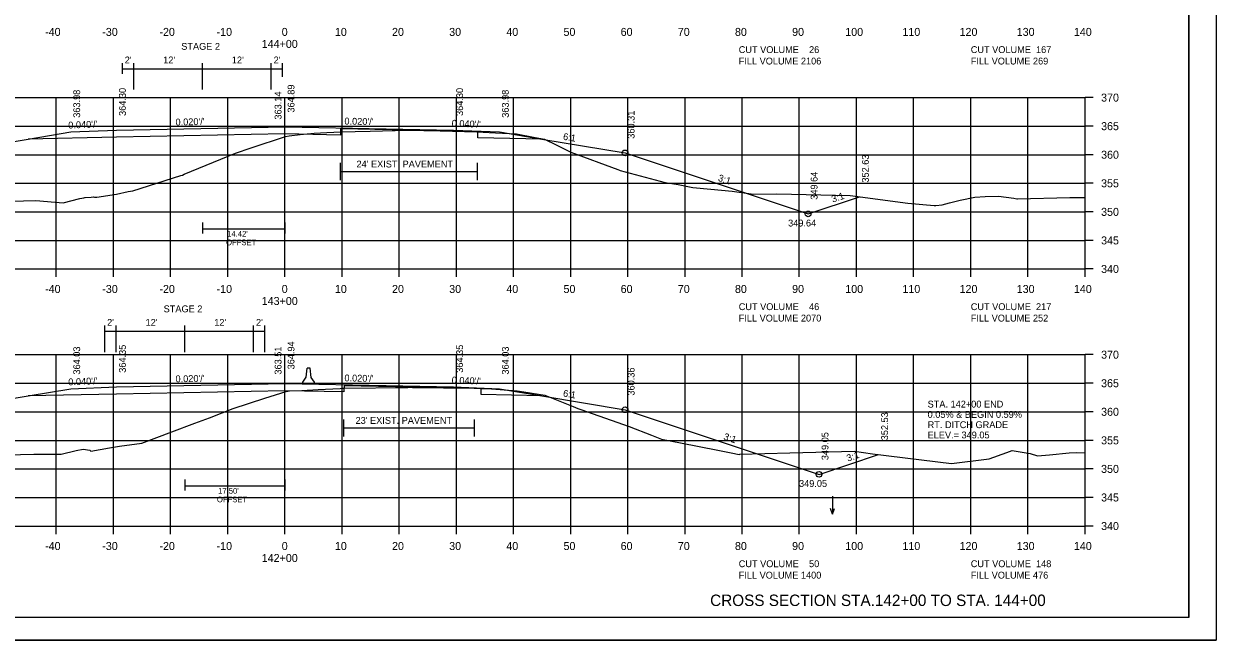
# Model space of a CAD drawing. Extents: x 1374859 to 1376773, y 382242 to 389804.
# Drawn here: x 1376088.9 to 1376297.5, y 386081.8 to 386189.7 of the extents above; entities that cross this region are included whole.
import ezdxf

# ---------------------------------------------------------------- set-up
doc = ezdxf.new("R2010")
doc.units = 0
for name, color, linetype in [('R_Axis', 7, 'Continuous'), ('R_Axis Annot', 7, 'Continuous'), ('R_Border', 7, 'Continuous'), ('R_Border Notes', 7, 'Continuous'), ('R_Detour Annot', 7, 'Continuous'), ('R_Draft', 7, 'Continuous'), ('R_Exist Surface', 7, 'Continuous'), ('R_Fin Surface', 7, 'Continuous'), ('R_Grid', 7, 'Continuous'), ('R_MOT', 7, 'Continuous'), ('R_No Plot', 7, 'Continuous'), ('R_Water Annot', 7, 'Continuous'), ('R_Xsect Elev', 7, 'Continuous'), ('R_Xsect Slope', 7, 'Continuous')]:
    doc.layers.add(name, color=color, linetype=linetype)

msp = doc.modelspace()

# ---------------------------------------------------------------- linework, layer by layer
at = {"layer": 'R_Axis'}
for p, q in [((1376274.57, 386146.8), (1376274.57, 386176.8)), ((1376275.97, 386176.8), (1376274.57, 386176.8)), ((1376275.97, 386171.8), (1376274.57, 386171.8)), ((1376275.97, 386166.8), (1376274.57, 386166.8)), ((1376275.97, 386161.8), (1376274.57, 386161.8)), ((1376275.97, 386156.8), (1376274.57, 386156.8)), ((1376275.97, 386151.8), (1376274.57, 386151.8)), ((1375994.57, 386146.8), (1376274.57, 386146.8)), ((1376094.57, 386145.4), (1376094.57, 386146.8)), ((1376104.57, 386145.4), (1376104.57, 386146.8)), ((1376114.57, 386145.4), (1376114.57, 386146.8)), ((1376124.57, 386145.4), (1376124.57, 386146.8)), ((1376134.57, 386145.4), (1376134.57, 386146.8)), ((1376144.57, 386145.4), (1376144.57, 386146.8)), ((1376154.57, 386145.4), (1376154.57, 386146.8)), ((1376164.57, 386145.4), (1376164.57, 386146.8)), ((1376174.57, 386145.4), (1376174.57, 386146.8)), ((1376184.57, 386145.4), (1376184.57, 386146.8)), ((1376194.57, 386145.4), (1376194.57, 386146.8)), ((1376204.57, 386145.4), (1376204.57, 386146.8)), ((1376214.57, 386145.4), (1376214.57, 386146.8)), ((1376224.57, 386145.4), (1376224.57, 386146.8)), ((1376234.57, 386145.4), (1376234.57, 386146.8)), ((1376244.57, 386145.4), (1376244.57, 386146.8)), ((1376254.57, 386145.4), (1376254.57, 386146.8)), ((1376264.57, 386145.4), (1376264.57, 386146.8)), ((1376274.57, 386145.4), (1376274.57, 386146.8)), ((1376275.97, 386146.8), (1376274.57, 386146.8)), ((1376274.57, 386101.8), (1376274.57, 386131.8)), ((1376275.97, 386131.8), (1376274.57, 386131.8)), ((1376275.97, 386126.8), (1376274.57, 386126.8)), ((1376275.97, 386121.8), (1376274.57, 386121.8)), ((1376275.97, 386116.8), (1376274.57, 386116.8)), ((1376275.97, 386111.8), (1376274.57, 386111.8)), ((1376275.97, 386106.8), (1376274.57, 386106.8)), ((1375994.57, 386101.8), (1376274.57, 386101.8)), ((1376094.57, 386100.4), (1376094.57, 386101.8)), ((1376104.57, 386100.4), (1376104.57, 386101.8)), ((1376114.57, 386100.4), (1376114.57, 386101.8)), ((1376124.57, 386100.4), (1376124.57, 386101.8)), ((1376134.57, 386100.4), (1376134.57, 386101.8)), ((1376144.57, 386100.4), (1376144.57, 386101.8)), ((1376154.57, 386100.4), (1376154.57, 386101.8)), ((1376164.57, 386100.4), (1376164.57, 386101.8)), ((1376174.57, 386100.4), (1376174.57, 386101.8)), ((1376184.57, 386100.4), (1376184.57, 386101.8)), ((1376194.57, 386100.4), (1376194.57, 386101.8)), ((1376204.57, 386100.4), (1376204.57, 386101.8)), ((1376214.57, 386100.4), (1376214.57, 386101.8)), ((1376224.57, 386100.4), (1376224.57, 386101.8)), ((1376234.57, 386100.4), (1376234.57, 386101.8)), ((1376244.57, 386100.4), (1376244.57, 386101.8)), ((1376254.57, 386100.4), (1376254.57, 386101.8)), ((1376264.57, 386100.4), (1376264.57, 386101.8)), ((1376274.57, 386100.4), (1376274.57, 386101.8)), ((1376275.97, 386101.8), (1376274.57, 386101.8))]:
    msp.add_line(p, q, dxfattribs=at)
at = {"layer": 'R_Border'}
for q in [(1376292.75, 386291.26), (1375976.57, 386085.8)]:
    msp.add_line((1376292.75, 386085.8), q, dxfattribs=at)
at = {"layer": 'R_Border Notes'}
for points in [[(1376144.22, 386165.36), (1376144.22, 386162.36)], [(1376168.22, 386165.36), (1376168.22, 386162.36)], [(1376144.22, 386163.86), (1376168.22, 386163.86)], [(1376144.8, 386120.47), (1376144.8, 386117.47)], [(1376167.68, 386120.47), (1376167.68, 386117.47)], [(1376144.8, 386118.97), (1376167.68, 386118.97)]]:
    msp.add_lwpolyline(points, dxfattribs=at)
at = {"layer": 'R_Exist Surface'}
for points in [[(1376084.38, 386158.61), (1376091.01, 386158.77), (1376094.38, 386158.51), (1376095.79, 386158.4), (1376098.7, 386159.11), (1376099.41, 386159.28), (1376099.54, 386159.3), (1376099.62, 386159.31), (1376100.67, 386159.38), (1376101.05, 386159.41), (1376101.24, 386159.4), (1376101.64, 386159.38), (1376105.08, 386159.91), (1376107.16, 386160.35), (1376107.96, 386160.48), (1376116.38, 386163.16), (1376116.67, 386163.25), (1376116.95, 386163.37), (1376125.91, 386167.07), (1376128.66, 386167.99), (1376134.69, 386169.99), (1376135.3, 386170.08), (1376137.22, 386170.35), (1376139.67, 386170.55), (1376141.93, 386170.71), (1376143.11, 386170.76), (1376144.22, 386170.79), (1376149.46, 386170.94), (1376156.01, 386171.11), (1376161.75, 386170.97), (1376168.17, 386170.81), (1376171.42, 386170.64), (1376175.1, 386170.45), (1376178.37, 386169.82), (1376179.99, 386169.51), (1376182.12, 386168.47), (1376184.6, 386167.27), (1376192.82, 386164.21), (1376193.09, 386164.11), (1376193.25, 386164.06), (1376201.07, 386161.91), (1376203.37, 386161.57), (1376205.92, 386161.06), (1376209.08, 386160.78), (1376212.82, 386160.41), (1376216.56, 386159.91), (1376220.61, 386159.97), (1376233.45, 386159.65), (1376243.55, 386158.33), (1376248.14, 386157.92), (1376248.43, 386157.94), (1376249.54, 386158.02), (1376250.83, 386158.38), (1376252.73, 386158.87), (1376255.27, 386159.4), (1376257.06, 386159.47), (1376259.45, 386159.53), (1376262.1, 386159.17), (1376262.62, 386159.08), (1376262.69, 386159.08), (1376262.74, 386159.08), (1376271.9, 386159.31), (1376273.73, 386159.29), (1376274.57, 386159.3)], [(1376085.96, 386114.27), (1376090.64, 386114.37), (1376094.67, 386114.41), (1376095.43, 386114.4), (1376098.04, 386115.01), (1376099.27, 386115.28), (1376099.29, 386115.27), (1376100.42, 386115.06), (1376100.62, 386114.92), (1376103.87, 386115.51), (1376105.65, 386115.81), (1376109.56, 386116.32), (1376114.81, 386118.27), (1376118.82, 386119.8), (1376121.4, 386120.77), (1376125.51, 386122.36), (1376131.06, 386124.17), (1376134.77, 386125.38), (1376135.39, 386125.44), (1376137.55, 386125.55), (1376140.4, 386125.7), (1376144.25, 386125.9), (1376144.57, 386125.91), (1376144.8, 386125.91), (1376156.07, 386126.08), (1376156.5, 386126.09), (1376156.9, 386126.08), (1376167.68, 386125.93), (1376168.91, 386125.9), (1376169.23, 386125.9), (1376169.93, 386125.85), (1376175.22, 386125.48), (1376176.39, 386125.29), (1376180.07, 386124.7), (1376185.01, 386122.7), (1376185.84, 386122.38), (1376186.37, 386122.19), (1376194.78, 386119.21), (1376198.68, 386117.72), (1376200.48, 386117.02), (1376203.79, 386116.39), (1376210.32, 386115.08), (1376212.66, 386114.6), (1376214.04, 386114.32), (1376214.17, 386114.38), (1376222.93, 386114.59), (1376234.22, 386114.89), (1376237.36, 386114.46), (1376251.18, 386112.75), (1376257.8, 386113.58), (1376260.89, 386114.67), (1376261.84, 386115), (1376264.97, 386114.48), (1376266.22, 386114.07), (1376268.37, 386114.29), (1376271.8, 386114.63), (1376273.04, 386114.65), (1376274.57, 386114.59)]]:
    msp.add_lwpolyline(points, dxfattribs=at)
at = {"layer": 'R_Fin Surface'}
for points in [[(1376040.79, 386158.31), (1376044.72, 386157), (1376075.09, 386167.12), (1376089.65, 386169.55), (1376097.09, 386170.78), (1376105.09, 386171.1), (1376134.59, 386171.69), (1376164.09, 386171.1), (1376172.09, 386170.78), (1376179.52, 386169.55), (1376194.09, 386167.12), (1376226.11, 386156.44), (1376235.08, 386159.43)], [(1376134.58, 386170.44), (1376105.1, 386169.85), (1376089.65, 386169.55)], [(1376179.52, 386169.55), (1376168.33, 386169.77), (1376168.32, 386170.85), (1376144.32, 386171.33), (1376144.31, 386170.25), (1376134.58, 386170.44)], [(1376037.31, 386114.03), (1376044.01, 386111.8), (1376075.09, 386122.16), (1376089.65, 386124.59), (1376097.09, 386125.83), (1376105.09, 386126.15), (1376134.59, 386126.74), (1376164.09, 386126.15), (1376172.09, 386125.83), (1376179.52, 386124.59), (1376194.09, 386122.16), (1376228.02, 386110.85), (1376238.44, 386114.33)], [(1376179.52, 386124.59), (1376168.92, 386124.8), (1376168.91, 386125.89), (1376144.91, 386126.37), (1376144.9, 386125.28), (1376134.58, 386125.49)], [(1376134.58, 386125.49), (1376105.1, 386124.9), (1376089.65, 386124.59)]]:
    msp.add_lwpolyline(points, dxfattribs=at)
at = {"layer": 'R_Grid'}
for p, q in [((1375994.57, 386176.8), (1376274.57, 386176.8)), ((1376094.57, 386146.8), (1376094.57, 386176.8)), ((1376104.57, 386146.8), (1376104.57, 386176.8)), ((1376114.57, 386146.8), (1376114.57, 386176.8)), ((1376124.57, 386146.8), (1376124.57, 386176.8)), ((1376134.57, 386146.8), (1376134.57, 386176.8)), ((1376144.57, 386146.8), (1376144.57, 386176.8)), ((1376154.57, 386146.8), (1376154.57, 386176.8)), ((1376164.57, 386146.8), (1376164.57, 386176.8)), ((1376174.57, 386146.8), (1376174.57, 386176.8)), ((1376184.57, 386146.8), (1376184.57, 386176.8)), ((1376194.57, 386146.8), (1376194.57, 386176.8)), ((1376204.57, 386146.8), (1376204.57, 386176.8)), ((1376214.57, 386146.8), (1376214.57, 386176.8)), ((1376224.57, 386146.8), (1376224.57, 386176.8)), ((1376234.57, 386146.8), (1376234.57, 386176.8)), ((1376244.57, 386146.8), (1376244.57, 386176.8)), ((1376254.57, 386146.8), (1376254.57, 386176.8)), ((1376264.57, 386146.8), (1376264.57, 386176.8)), ((1376274.57, 386146.8), (1376274.57, 386176.8)), ((1375994.57, 386171.8), (1376274.57, 386171.8)), ((1375994.57, 386166.8), (1376274.57, 386166.8)), ((1375994.57, 386161.8), (1376274.57, 386161.8)), ((1375994.57, 386156.8), (1376274.57, 386156.8)), ((1375994.57, 386151.8), (1376274.57, 386151.8)), ((1375994.57, 386146.8), (1376274.57, 386146.8)), ((1375994.57, 386131.8), (1376274.57, 386131.8)), ((1376094.57, 386101.8), (1376094.57, 386131.8)), ((1376104.57, 386101.8), (1376104.57, 386131.8)), ((1376114.57, 386101.8), (1376114.57, 386131.8)), ((1376124.57, 386101.8), (1376124.57, 386131.8)), ((1376134.57, 386101.8), (1376134.57, 386131.8)), ((1376144.57, 386101.8), (1376144.57, 386131.8)), ((1376154.57, 386101.8), (1376154.57, 386131.8)), ((1376164.57, 386101.8), (1376164.57, 386131.8)), ((1376174.57, 386101.8), (1376174.57, 386131.8)), ((1376184.57, 386101.8), (1376184.57, 386131.8)), ((1376194.57, 386101.8), (1376194.57, 386131.8)), ((1376204.57, 386101.8), (1376204.57, 386131.8)), ((1376214.57, 386101.8), (1376214.57, 386131.8)), ((1376224.57, 386101.8), (1376224.57, 386131.8)), ((1376234.57, 386101.8), (1376234.57, 386131.8)), ((1376244.57, 386101.8), (1376244.57, 386131.8)), ((1376254.57, 386101.8), (1376254.57, 386131.8)), ((1376264.57, 386101.8), (1376264.57, 386131.8)), ((1376274.57, 386101.8), (1376274.57, 386131.8)), ((1375994.57, 386126.8), (1376274.57, 386126.8)), ((1375994.57, 386121.8), (1376274.57, 386121.8)), ((1375994.57, 386116.8), (1376274.57, 386116.8)), ((1375994.57, 386111.8), (1376274.57, 386111.8)), ((1375994.57, 386106.8), (1376274.57, 386106.8)), ((1375994.57, 386101.8), (1376274.57, 386101.8))]:
    msp.add_line(p, q, dxfattribs=at)
at = {"layer": 'R_MOT'}
for p, q in [((1376106.15, 386180.94), (1376106.15, 386182.84)), ((1376108.15, 386178.2), (1376108.15, 386182.84)), ((1376120.15, 386178.2), (1376120.15, 386182.84)), ((1376132.15, 386178.2), (1376132.15, 386182.84)), ((1376134.15, 386180.41), (1376134.15, 386182.84)), ((1376106.15, 386181.84), (1376134.15, 386181.84)), ((1376120.15, 386154.94), (1376120.15, 386153.01)), ((1376134.57, 386154.94), (1376134.57, 386153.01)), ((1376134.57, 386153.76), (1376120.15, 386153.76)), ((1376103.07, 386132.25), (1376103.07, 386136.89)), ((1376105.07, 386132.25), (1376105.07, 386136.89)), ((1376117.07, 386132.25), (1376117.07, 386136.89)), ((1376129.07, 386132.25), (1376129.07, 386136.89)), ((1376131.07, 386132.25), (1376131.07, 386136.89)), ((1376103.07, 386135.89), (1376131.07, 386135.89)), ((1376137.73, 386127), (1376138.3, 386127.84)), ((1376138.3, 386127.84), (1376138.47, 386129.42)), ((1376138.72, 386129.42), (1376138.47, 386129.42)), ((1376138.97, 386129.42), (1376138.72, 386129.42)), ((1376139.14, 386127.83), (1376138.97, 386129.42)), ((1376139.73, 386127), (1376139.14, 386127.83)), ((1376137.72, 386126.67), (1376137.73, 386127)), ((1376139.72, 386126.67), (1376137.72, 386126.67)), ((1376139.72, 386126.67), (1376139.73, 386127)), ((1376117.07, 386109.94), (1376117.07, 386108.01)), ((1376134.57, 386109.94), (1376134.57, 386108.01)), ((1376134.57, 386108.76), (1376117.07, 386108.76))]:
    msp.add_line(p, q, dxfattribs=at)
at = {"layer": 'R_No Plot'}
msp.add_line((1375964.17, 386081.83), (1376297.5, 386081.83), dxfattribs=at)
for points in [[(1375964.16, 386295.16), (1376297.5, 386295.16), (1376297.5, 386081.82), (1375964.16, 386081.82)], [(1376210.49, 386291.26), (1376210.49, 386281.38), (1376246.22, 386281.38), (1376246.22, 386278.46), (1376269.42, 386278.46), (1376269.42, 386254.13), (1376292.75, 386254.13), (1376292.75, 386085.8), (1375976.57, 386085.8), (1375976.57, 386291.26)]]:
    msp.add_lwpolyline(points, close=True, dxfattribs=at)
for centre in [(1376194.09, 386167.12), (1376226.11, 386156.44), (1376194.09, 386122.16), (1376228.02, 386110.85)]:
    msp.add_circle(centre, 0.5, dxfattribs=at)
at = {"layer": 'R_Water Annot'}
for p, q in [((1376230.37, 386107.04), (1376230.37, 386103.9)), ((1376230.37, 386103.9), (1376230.02, 386104.86)), ((1376230.37, 386103.9), (1376230.72, 386104.86))]:
    msp.add_line(p, q, dxfattribs=at)

# ---------------------------------------------------------------- texts
at = {"layer": 'R_Axis Annot'}
for s, height, p in [('-40', 1.4, (1376092.61, 386187.6)), ('-30', 1.4, (1376102.61, 386187.6)), ('-20', 1.4, (1376112.61, 386187.6)), ('-10', 1.4, (1376122.61, 386187.6)), ('0', 1.4, (1376134.01, 386187.6)), ('10', 1.4, (1376143.31, 386187.6)), ('20', 1.4, (1376153.31, 386187.6)), ('30', 1.4, (1376163.31, 386187.6)), ('40', 1.4, (1376173.31, 386187.6)), ('50', 1.4, (1376183.31, 386187.6)), ('60', 1.4, (1376193.31, 386187.6)), ('70', 1.4, (1376203.31, 386187.6)), ('80', 1.4, (1376213.31, 386187.6)), ('90', 1.4, (1376223.31, 386187.6)), ('100', 1.4, (1376232.61, 386187.6)), ('110', 1.4, (1376242.61, 386187.6)), ('120', 1.4, (1376252.61, 386187.6)), ('130', 1.4, (1376262.61, 386187.6)), ('140', 1.4, (1376272.61, 386187.6)), ('144+00', 1.4, (1376130.51, 386185.5)), ('CUT VOLUME    26', 1.2, (1376213.97, 386184.6)), ('CUT VOLUME  167', 1.2, (1376254.57, 386184.6)), ('FILL VOLUME 2106', 1.2, (1376213.97, 386182.6)), ('FILL VOLUME 269', 1.2, (1376254.57, 386182.6)), ('370', 1.4, (1376277.37, 386176.1)), ('365', 1.4, (1376277.37, 386171.1)), ('360', 1.4, (1376277.37, 386166.1)), ('355', 1.4, (1376277.37, 386161.1)), ('350', 1.4, (1376277.37, 386156.1)), ('345', 1.4, (1376277.37, 386151.1)), ('340', 1.4, (1376277.37, 386146.1)), ('-40', 1.4, (1376092.61, 386142.6)), ('-30', 1.4, (1376102.61, 386142.6)), ('-20', 1.4, (1376112.61, 386142.6)), ('-10', 1.4, (1376122.61, 386142.6)), ('0', 1.4, (1376134.01, 386142.6)), ('10', 1.4, (1376143.31, 386142.6)), ('20', 1.4, (1376153.31, 386142.6)), ('30', 1.4, (1376163.31, 386142.6)), ('40', 1.4, (1376173.31, 386142.6)), ('50', 1.4, (1376183.31, 386142.6)), ('60', 1.4, (1376193.31, 386142.6)), ('70', 1.4, (1376203.31, 386142.6)), ('80', 1.4, (1376213.31, 386142.6)), ('90', 1.4, (1376223.31, 386142.6)), ('100', 1.4, (1376232.61, 386142.6)), ('110', 1.4, (1376242.61, 386142.6)), ('120', 1.4, (1376252.61, 386142.6)), ('130', 1.4, (1376262.61, 386142.6)), ('140', 1.4, (1376272.61, 386142.6)), ('143+00', 1.4, (1376130.51, 386140.5)), ('CUT VOLUME    46', 1.2, (1376213.97, 386139.6)), ('CUT VOLUME  217', 1.2, (1376254.57, 386139.6)), ('FILL VOLUME 2070', 1.2, (1376213.97, 386137.6)), ('FILL VOLUME 252', 1.2, (1376254.57, 386137.6)), ('370', 1.4, (1376277.37, 386131.1)), ('365', 1.4, (1376277.37, 386126.1)), ('360', 1.4, (1376277.37, 386121.1)), ('355', 1.4, (1376277.37, 386116.1)), ('350', 1.4, (1376277.37, 386111.1)), ('345', 1.4, (1376277.37, 386106.1)), ('340', 1.4, (1376277.37, 386101.1)), ('-40', 1.4, (1376092.61, 386097.6)), ('-30', 1.4, (1376102.61, 386097.6)), ('-20', 1.4, (1376112.61, 386097.6)), ('-10', 1.4, (1376122.61, 386097.6)), ('0', 1.4, (1376134.01, 386097.6)), ('10', 1.4, (1376143.31, 386097.6)), ('20', 1.4, (1376153.31, 386097.6)), ('30', 1.4, (1376163.31, 386097.6)), ('40', 1.4, (1376173.31, 386097.6)), ('50', 1.4, (1376183.31, 386097.6)), ('60', 1.4, (1376193.31, 386097.6)), ('70', 1.4, (1376203.31, 386097.6)), ('80', 1.4, (1376213.31, 386097.6)), ('90', 1.4, (1376223.31, 386097.6)), ('100', 1.4, (1376232.61, 386097.6)), ('110', 1.4, (1376242.61, 386097.6)), ('120', 1.4, (1376252.61, 386097.6)), ('130', 1.4, (1376262.61, 386097.6)), ('140', 1.4, (1376272.61, 386097.6)), ('142+00', 1.4, (1376130.51, 386095.5)), ('CUT VOLUME    50', 1.2, (1376213.97, 386094.6)), ('CUT VOLUME  148', 1.2, (1376254.57, 386094.6)), ('FILL VOLUME 1400', 1.2, (1376213.97, 386092.6)), ('FILL VOLUME 476', 1.2, (1376254.57, 386092.6))]:
    msp.add_text(s, height=height, dxfattribs=at).set_placement(p)
at = {"layer": 'R_Border Notes'}
for s, p in [("24' EXIST. PAVEMENT", (1376147.09, 386164.57)), ("23' EXIST. PAVEMENT", (1376146.93, 386119.69))]:
    msp.add_text(s, height=1.2, rotation=0, dxfattribs=at).set_placement(p)
at = {"layer": 'R_Detour Annot'}
for s, p in [('STA. 142+00 END', (1376247.02, 386122.54)), ('0.05% & BEGIN 0.59%', (1376247.02, 386120.74)), ('RT. DITCH GRADE', (1376247.02, 386118.94)), ('ELEV.= 349.05', (1376247.02, 386117.14))]:
    msp.add_text(s, height=1.2, dxfattribs=at).set_placement(p)
at = {"layer": 'R_Draft'}
for s, height, p in [("14.42'", 1, (1376124.47, 386152.46)), ('OFFSET', 1, (1376124.27, 386150.96)), ('OFFSET', 1, (1376122.68, 386105.96)), ("17.50'", 1, (1376122.89, 386107.46)), ('CROSS SECTION STA.142+00 TO STA. 144+00', 2, (1376208.97, 386087.8))]:
    msp.add_text(s, height=height, dxfattribs=at).set_placement(p)
at = {"layer": 'R_MOT'}
for p in [(1376116.43, 386185.17), (1376113.35, 386139.22)]:
    msp.add_text('STAGE 2', height=1.2, rotation=0, dxfattribs=at).set_placement(p)
for s, p in [("2'", (1376106.54, 386182.79)), ("12'", (1376113.27, 386182.79)), ("12'", (1376125.28, 386182.79)), ("2'", (1376132.59, 386182.79)), ("2'", (1376103.46, 386136.85)), ("12'", (1376110.19, 386136.85)), ("12'", (1376122.2, 386136.85)), ("2'", (1376129.51, 386136.85))]:
    msp.add_text(s, height=1.2, dxfattribs=at).set_placement(p)
at = {"layer": 'R_Xsect Elev'}
for s, p in [('363.98', (1376098.74, 386173.27)), ('364.30', (1376106.74, 386173.59)), ('364.89', (1376136.24, 386174.18)), ('364.30', (1376165.74, 386173.59)), ('363.98', (1376173.74, 386173.27)), ('363.14', (1376133.97, 386172.95)), ('360.31', (1376195.74, 386169.6)), ('352.63', (1376236.73, 386161.92)), ('349.64', (1376227.76, 386158.92)), ('364.94', (1376136.24, 386129.22)), ('364.03', (1376098.74, 386128.31)), ('364.35', (1376106.74, 386128.63)), ('363.51', (1376133.97, 386128.31)), ('364.35', (1376165.74, 386128.63)), ('364.03', (1376173.74, 386128.31)), ('360.36', (1376195.74, 386124.64)), ('352.53', (1376240.1, 386116.81)), ('349.05', (1376229.67, 386113.33))]:
    msp.add_text(s, height=1.2, rotation=90, dxfattribs=at).set_placement(p)
for s, p in [('349.64', (1376222.61, 386154.24)), ('349.05', (1376224.52, 386108.65))]:
    msp.add_text(s, height=1.2, dxfattribs=at).set_placement(p)
at = {"layer": 'R_Xsect Slope'}
for s, rotation, p in [("0.040'/'", 2.2906, (1376096.69, 386171.37)), ("0.020'/'", 1.1458, (1376115.44, 386171.91)), ("0.020'/'", 358.8542, (1376144.97, 386172.09)), ("0.040'/'", 357.7094, (1376163.73, 386171.72)), ('6:1', 350.5358, (1376183.17, 386169.44)), ('3:1', 341.5651, (1376210.25, 386162.26)), ('3:1', 18.4349, (1376230.43, 386158.41)), ("0.040'/'", 2.2906, (1376096.69, 386126.42)), ("0.020'/'", 1.1458, (1376115.44, 386126.96)), ("0.020'/'", 358.8542, (1376144.97, 386127.13)), ("0.040'/'", 357.7094, (1376163.73, 386126.77)), ('6:1', 350.5358, (1376183.17, 386124.49)), ('3:1', 341.5651, (1376211.21, 386116.98)), ('3:1', 18.4349, (1376233.07, 386113.07))]:
    msp.add_text(s, height=1.2, rotation=rotation, dxfattribs=at).set_placement(p)

doc.saveas('drawing.dxf')
